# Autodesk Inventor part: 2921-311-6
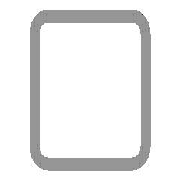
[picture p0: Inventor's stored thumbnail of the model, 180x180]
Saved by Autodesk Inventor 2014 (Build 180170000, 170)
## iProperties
IsCustomPart: 1
Company: NHTSA/VRTC
Created: 2012-02
Part Number: 2921-311-6
Material: Steel, Mild
Description: BENCH FRAME TUBE #6
Document SubType Name: Modeling
Standard: AISC
Designer: Dave Walker
Standards Organization: ANSI
Language: en-US
Size Designation: 1-1/2x1-1/2x1/8 - 5
Categories: <MemberInstance><Categories><Category DisplayName="Structural Shapes" InternalName="089c4875-fa83-4c05-b084-43b9cc11f5ed" Mnemonic="GRDR"><CategoryParameter Dis
Stock Number: T.S. 1 1/2 x 1 1/2 x 1/8 x 127.0mm (5.0")
Density: 1 g/cm^3
Project: CHILD SIDE IMPACT SLED
Appearance: Steel
G_L: 5.000 in
Author: Dave Walker
Title: Bench Frame Tube #6
Subject: Child Side Impact Sled
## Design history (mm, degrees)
node "Start plane"
node "End plane"
sketch "Sketch"
  geometry: L1 (-19.05, -12.7)-(-19.05, 12.7); L2 (-12.7, 19.05)-(12.7, 19.05); L3 (19.05, 12.7)-(19.05, -12.7); L4 (12.7, -19.05)-(-12.7, -19.05); L5 (-12.7, 15.875)-(12.7, 15.875); L6 (15.875, 12.7)-(15.875, -12.7); L7 (12.7, -15.875)-(-12.7, -15.875); L8 (-15.875, -12.7)-(-15.875, 12.7); L9 (0, 36.948)-(0, -36.948) reference; L10 (-23.079, 0)-(23.079, 0) reference; A1 r 6.35 centre (-12.7, -12.7) between (-19.05, -12.7) and (-12.7, -19.05); A2 r 6.35 centre (-12.7, 12.7) between (-12.7, 19.05) and (-19.05, 12.7); A3 r 6.35 centre (12.7, 12.7) between (19.05, 12.7) and (12.7, 19.05); A4 r 6.35 centre (12.7, -12.7) between (12.7, -19.05) and (19.05, -12.7); A5 r 3.175 centre (-12.7, 12.7) between (-12.7, 15.875) and (-15.875, 12.7); A6 r 3.175 centre (12.7, 12.7) between (15.875, 12.7) and (12.7, 15.875); A7 r 3.175 centre (12.7, -12.7) between (12.7, -15.875) and (15.875, -12.7); A8 r 3.175 centre (-12.7, -12.7) between (-15.875, -12.7) and (-12.7, -15.875)
  constraints: 16 end point, 16 point on circle, 8 centre point, 8 tangent, 4 parallel, 3 equal radius, 2 perpendicular, 7 other
  dimensions: "d10" = 38.1 distance between parallel lines of L2 L4 (= G_H); "d11" = 38.1 distance between parallel lines of L1 L3 (= G_W); "d12" = 3.175 distance between parallel lines of L3 L6 (= G_T); "d15" = 19.05 distance between parallel lines of L2 L10 (= 0.5 x d10); "d16" = 19.05 distance between parallel lines of L9 L3 (= 0.5 x d11); "d17" = 6.35 radius of A1 (= G_IR)
extrude "Body" new body sketch "Sketch" stored distance "d3" = 127 (= G_L); taper "d4" = 0 deg
node "Driven Length"
  sketch "Sketch3"
    geometry: L1 (0, 0)-(10, 0) reference
    constraints: 2 end point, 1 horizontal
  workplane "Work Plane3"
  sketch "Sketch4"
    geometry: L1 (-2, 0)-(12, 0) reference; L2 (-2, 127)-(12, 127) reference
    dimensions: "d19" = 127 distance between parallel lines of L1 L2 (derived)
sketch "Sketch5"
  geometry: L1 (127, 31.75)-(0, 31.75) reference; L2 (127, -6.35)-(0, -6.35) reference; L3 (0, -6.35)-(10.209, 31.75); L4 (10.209, 31.75)-(0, 31.75); L5 (0, 31.75)-(0, -6.35); 1 further point
  constraints: 6 end point, 1 collinear, 1 perpendicular, 1 point on line
  dimensions: "d20" = 75 deg angle of L2 L3
extrude "Extrusion2" cut sketch "Sketch5" stored distance "d21" = 25.4; taper "d22" = 0 deg
body "Solid1"
other parameters: "G_W" = 38.1 [user parameter; used in 1 equation term], "G_H" = 38.1 [user parameter; used in 1 equation term], "G_T" = 3.175 [user parameter; used in 1 equation term], "G_IR" = 6.35 [user parameter; used in 1 equation term], "G_L" = 127 (= d19) [user parameter; used in 1 equation term], "G_OFFSET_START" = 0 [user parameter; used in 1 equation term], "G_OFFSET_END" = 0 [user parameter; used in 1 equation term], "d13" = 0 (computed from G_OFFSET_START), "d14" = 127 (= G_OFFSET_END + B_L), "B_L" = 127 [user parameter; used in 1 equation term], "d18" = 90 deg
